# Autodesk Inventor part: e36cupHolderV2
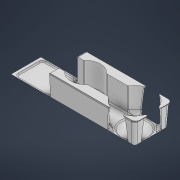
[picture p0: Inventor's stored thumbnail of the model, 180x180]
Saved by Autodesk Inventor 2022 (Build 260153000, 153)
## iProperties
Created: 2024-06
Part Number: e36cupHolderV2
Material: Všeobecné
Document SubType Name: Modeling
Designer: FIJI
Density: 1 g/cm^3
Appearance: Výchozí
Author: FIJI
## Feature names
1. Tažení1
2. Zaoblení2 [Fillet]
3. Zaoblení3 [Fillet]
4. Vysunutí3 [Extrusion]
5. Zaoblení4 [Fillet]
6. Vysunutí4 [Extrusion]
7. Vysunutí6 [Extrusion]
8. Zaoblení7 [Fillet]
9. Zaoblení8 [Fillet]
10. Vysunutí7 [Extrusion]
11. Vysunutí8 [Extrusion]
12. Vysunutí9 [Extrusion]
13. Zaoblení9 [Fillet]
## Parameters: d0 = 236.8 mm, d1 = 67.6 mm, d22 = 30.5 mm, d24 = 48 mm, d25 = 0, d26 = 0, d27 = 0.8 mm, d28 = 0.8 mm, d29 = 6 mm, d30 = 6 mm, d31 = 7 mm, d32 = 0.8 mm, d33 = 69 mm, d34 = 69 mm, d35 = 33.8 mm, d36 = 33.8 mm, d37 = 33.8 mm, d39 = 44 mm, d40 = 0, d41 = 5.8 mm, d42 = 1 mm, d43 = 13.82896 mm, d44 = 17.5 mm, d47 = 6 mm, d48 = 5.48551 mm, d49 = 4.8 mm, d50 = 4.8 mm, d51 = 4.8 mm, d54 = 2 mm, d55 = 0, d63 = 1.8 mm, d64 = 8 mm, d65 = 0.8 mm, d66 = 0, d71 = 13.82896 mm, d72 = 6.91448 mm, d73 = 1.8 mm, d74 = 1 mm, d75 = 5.8 mm, d76 = 2.4 mm, d77 = 2.4 mm, d78 = 2 mm, d80 = 0, d81 = 0, d82 = 1 mm, d86 = 1.4 mm, d87 = 45 deg, d88 = 0, d89 = 0, d90 = 45 deg, d91 = 0, d92 = 0, d93 = 4 mm, d94 = 54.6 mm, d95 = 52 mm, d96 = 49.4 mm, d97 = 1 mm, d98 = 2.4 mm, d100 = 2.4 mm, d101 = 1 mm
